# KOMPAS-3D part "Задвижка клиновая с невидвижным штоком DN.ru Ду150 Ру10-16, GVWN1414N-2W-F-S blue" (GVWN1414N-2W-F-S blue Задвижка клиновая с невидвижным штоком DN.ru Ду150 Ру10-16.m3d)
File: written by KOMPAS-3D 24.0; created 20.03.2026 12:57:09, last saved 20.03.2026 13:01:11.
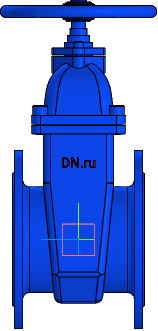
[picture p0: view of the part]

Document properties: Автор: R2D2; Полное имя файла: E:\Работа\Зайцев\GVWN1414N-2W-F-S blue Задвижка клиновая с невидвижным штоком DN.ru Ду40-300 Ру10-16\DN150\GVWN1414N-2W-F-S blue Задвижка клиновая с невидвижным штоком DN.ru Ду150 Ру10-16.m3d

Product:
- Part/product: Задвижка клиновая с невидвижным штоком DN.ru Ду150 Ру10-16  | designation GVWN1414N-2W-F-S blue
    Масса: 24
    Раздел спецификации: Прочие изделия
    Примечание: D040-10584

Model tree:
1. Операция без истории:2

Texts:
  GVWN1414N-2W-F-S blue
